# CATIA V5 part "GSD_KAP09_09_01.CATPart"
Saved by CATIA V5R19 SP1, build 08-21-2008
Part number: GSD_REPETITION_08
Description: Beispielmodell: PowerCopy verwenden  Maik Hertha IT Consultants
Bounding box of the stored display mesh (mm): x -41.815 to 61.922, y 85.542 to 127.106, z 68.249 to 109.813
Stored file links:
  C:\Users\Maik\CAD Daten\modelle\gsd_buch_uebung\GSD_KAP09_09_01.CATPart
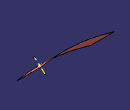
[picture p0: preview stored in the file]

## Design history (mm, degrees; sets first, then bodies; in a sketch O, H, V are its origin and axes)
AxisSystem1 "Absolute Axis System": origin (0, 0, 0), X (1, 0, 0), Y (0, 1, 0), Z (0, 0, 1)
Set1
  Plane1: type Equation, A 0, B 0.5, C 0.5, Length 80
  Point1: type OnPlane, Support Plane1, Direction (-1, 0, 0), H -16.666, V 8.006
  Set2 "Basisflaeche"
    Sketch1 on Plane1, origin (16.666, 74.3389, 85.6611), H (-1, 0, 0), V (0, -0.7071, 0.7071)
      spline S1 through (-45.2564, -18.0844) (-0.4529, -16.019) (58.4809, -24.6246)
      curve C1
    Extrude1: Lim1 50, Lim2 0, Element1 Sketch1.C1, Direction Plane1
  Point2 "Referenzpunkt": type OnSurface, Support Extrude1, Direction (0.984, -0.1774, 0.0196), Length 32.611
  Line1 "Ausrichtung": type Normal, RefSkin Extrude1, Start -10, End 10, RefPoint Point2
Body1 (main body)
